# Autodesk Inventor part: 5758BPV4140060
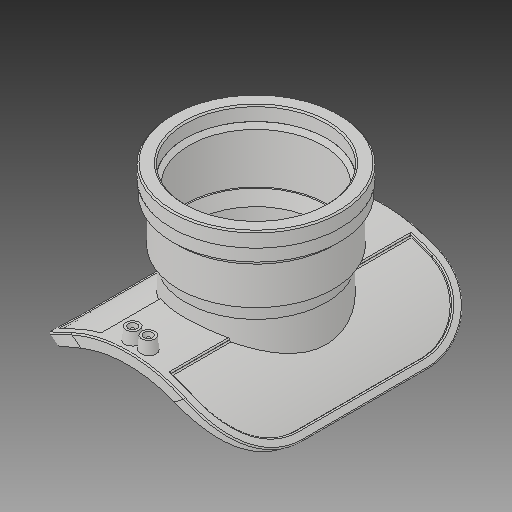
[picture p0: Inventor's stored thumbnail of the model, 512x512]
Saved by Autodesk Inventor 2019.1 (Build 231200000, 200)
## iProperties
Created: 2017-08
Part Number: 5758BPV4140060
Material: Generic
Description: PLASSON WASTEWATER SADDLE TEE 90 10''DIPS x 6''PSM for PVC
Document SubType Name: Modeling
Designer: Кирилл
Density: 1 g/cm^3
Appearance: Default
Author: Кирилл
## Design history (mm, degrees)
derived "5758BP.ipt"
feature "Solid1::5758BP.ipt"
feature "Solid2::5758BP.ipt"
feature "Solid3::5758BP.ipt"
tag "TaggingFeature1"
body "Solid1"
other parameters: "d0" = 280.6, "d1" = 246.888, "d2" = 305.854, "d3" = 289.56, "d4" = 0, "d5" = 74.0664, "d6" = 9.546, "d7" = 30 deg, "d8" = 15 deg, "d10" = 0, "d11" = 182.39, "d38" = 1.403, "d40" = 166.3, "d41" = 15, "d42" = 130.302, "d43" = 17.501, "d44" = 8.7505, "d46" = 5 deg, "d47" = 4, "d49" = 4, "d51" = 14, "d52" = 0, "d53" = 3, "d54" = 0, "d56" = 159.1, "d57" = 0.5, "d58" = 80.01, "d59" = 16.002, "d60" = 5.6007, "d61" = 40 deg, "d62" = 151.145, "d63" = 155.918, "d64" = 143.19, "d65" = 155 deg, "d66" = 124.968, "d67" = 189.992, "d68" = 188.09208, "d69" = 45 deg, "d70" = 174.546, "d72" = 7.723, "d75" = 0, "d77" = 0, "d78" = 1.591, "d81" = 37.4904, "d_" = 280.6, "B_" = 246.888, "H_" = 124.968, "L_" = 289.56, "d_1" = 159.1, "D_" = 189.992, "L_1" = 80.01, "d71" = 7.723
